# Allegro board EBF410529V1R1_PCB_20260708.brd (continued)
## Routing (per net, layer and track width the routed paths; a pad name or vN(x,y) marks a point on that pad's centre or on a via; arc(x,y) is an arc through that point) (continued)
VBUS5V0_TYPEC: length 54
  TOP w0.254: J10.B9 v1(29.3,86.28) v1(29.3,87.05) 30.12,87.05 v1(30.12,87.05) ; v1(29.25,80.59) v1(29.25,81.33) v1(29.25,82.13) 29.06,82.32 J10.A4 ; J10.B4 26.8,85.95 v1(26.54,86.21) v1(26.54,87.01) v1(25.74,87.01) ; J10.A9 26.56,82.25 v1(26.41,82.1) v1(26.41,81.3) v1(26.41,80.59)
  ART03 w0.254: v1(53.54,84.99) 53.16,84.61 50.47,84.61 48.51,82.65 45.75,82.65 44.37,84.02 36.47,84.02 33.05,80.59 v1(29.25,80.59)
  BOTTOM w0.254: v1(26.41,81.3) v1(26.41,82.1)
  BOTTOM w0.3: v1(53.54,84.99) 53.54,80.29 51.99,78.74 51.99,72.57 51.69,72.26 U11.2
VCC3V3_RTC_S5: length 27
  ART03 w0.381: v1(7.87,52.96) 7.87,56.06 6.96,56.97 3.84,56.97 2.92,57.89 v1(2.92,59.65)
  BOTTOM w0.254: U6.2 v1(2.92,59.65) ; R241.1 14.34,50.93 13.34,50.93 13.08,51.18 13.08,53.04 12.17,53.95 8.26,53.95 7.87,53.57 v1(7.87,52.96)
  BOTTOM w0.381: U6.2 3.75,60.51 C31.1 3.75,61.41 D9.2
VCC5V0_SYS_S5: length 253.3
  TOP w0.254: J3.6 15.69,60.8 15.44,60.55 J3.5 ; v1(23.5,49.5) 22.86,50.14 R198.2 ; J3.1 14.44,60.67 14.69,60.92 J3.2 ; v1(23.02,22.54) 21.7,22.54 19,19.83 19,16.92 20.73,15.19 v1(20.73,13.47) ; J3.7 15.94,60.49 16.19,60.74 J3.8 ; J3.3 14.94,60.61 15.19,60.86 J3.4
  TOP w0.381: J3.2 14.69,66.21 14.2,66.7 11.07,66.7 10.54,66.17 10.54,64.85 9.93,64.24 7.32,64.24 5.21,62.13 2.92,62.13 1.57,60.78 1.57,55.15 v2(2.29,54.43)
  BOTTOM w0.254: R6.2 C11.2 19.12,55.67 17.92,54.47 17.92,53.9 17.62,53.59 15.96,53.59 ; v1(20.73,13.47) 21.11,13.09 38.12,13.09 38.96,12.24 38.96,8.69 40.34,7.32 40.34,4.62 43.59,1.37 65.74,1.37 66.9,2.54 106.6,2.54 109.96,5.89 135,5.89 136.27,4.62 R4.1 ; v1(23.02,22.54) 22.78,22.77 22.78,43.97 23.5,44.68 v1(23.5,49.5) 21.41,51.58 16.74,51.58 15.82,52.5 v1(15.64,52.5)
  BOTTOM w0.381: v2(2.29,54.43) C32.1 2.29,56.32 2.79,56.82 U6.3
  vias: v1(14.84,54.1) v1(14.84,53.3) v1(14.84,52.5) v1(15.64,54.1) v1(15.64,53.3)
VCC5V0_USB20_HOST: length 24.3
  ART03 w0.762: J12.1 J12.7 135.44,80.42 129.49,80.42 128.14,79.07 120.2,79.07 118.31,77.18 J11.10
VCC_1V8_S3: length 60.5
  TOP w0.254: R159.1 v1(76.78,35.43) ; v1(61.78,36.3) 61.8,36.27 61.8,35.86 R158.1 ; J3.26 20.69,60.11 20.44,59.86 J3.25 v1(20.44,54.1)
  TOP w0.508: v1(93.01,27) 93.04,26.97 93.04,20.62 89.43,17.02 C133.1 C134.1 88.52,15.65 88.52,12.79 D58.2 93.72,5.82 J30.1
  ART03 w0.254: v1(20.44,52.1) 19.95,51.61 18.57,51.61 15.98,49.02 15.98,45.34 v1(15.49,44.85)
  PWR04 w0.254: v1(20.44,54.1) v1(20.44,53.1) v1(20.44,52.1)
  BOTTOM w0.254: R156.1 9.91,45.72 13.97,45.72 14.84,44.85 v1(15.49,44.85)
  vias: v1(92.21,27)
VCC_3V3_S0: length 30.3
  TOP w0.254: v1(18.44,54.1) J3.17 18.44,60.15 18.69,60.4 J3.18 ; J3.16 18.19,60.46 17.94,60.21 J3.15
  PWR04 w0.254: v1(18.44,54.1) v1(18.44,53.1) v1(18.44,52.1)
  BOTTOM w0.254: v1(126.54,20.5) 126.54,19.99 128.45,18.09 129.33,18.09 C20.1 130.49,18.09 132,18.09 C21.1 132.74,18.51 J4.4
  vias: v1(13.89,46.65) v1(14.69,46.65) v1(14.69,45.85) v1(15.49,45.85)
VCC_RTC: length 22.2
  ART03 w0.381: v1(5.21,50.87) 5.01,50.87 1.68,54.2 1.68,62.5 v2(1.88,62.7)
  BOTTOM w0.305: U5.8 7.61,50.84 8.08,51.31 C26.1 ; R157.1 R32.1
  BOTTOM w0.381: D9.3 v2(1.88,62.7) ; v1(5.21,50.87) 5.79,50.28 R157.1 8.64,50.29 C26.1
VCCA1V8_PLDO2_S0: length 3.5
  TOP w0.305: J3.23 19.94,54.6 v1(19.44,54.1)
  BOTTOM w0.254: R15.1 42.16,62.11 41.83,62.44 v1(41.19,62.44)
VDD_3V3: length 137.4
  TOP w0.203: U7.28 67.17,24.36 C35.1 67.57,24.46 U7.29 ; U8.28 83.4,24.36 C50.1 83.8,24.46 U8.29
  TOP w0.254: C33.1 v1(67.32,22.53) C34.1 C35.1 ; R77.1 v1(76.78,34.42) ; R34.1 v1(63.25,20.21) ; R21.1 v1(140.72,6.46) ; R35.1 v1(61.21,20.21) ; C50.1 C51.1 v1(83.55,22.52) C49.1 ; C176.1 v1(5.08,75.29) ; R145.1 v1(138.68,23.76) ; R46.1 73.28,23.5 L5.1 ; R22.1 v1(135.24,8.13) ; v1(60.53,35.2) 60.75,35.42 R53.1 ; R33.1 v1(64.26,20.21) ; R72.1 v1(76.78,32.26) ; v1(80.49,20.21) R57.1 ; R70.1 89.51,23.5 L7.1 ; R141.1 v1(109.02,52.84) R142.1 ; v1(79.48,20.21) R58.1 ; R48.1 R47.1 60.63,31.24 v1(60.54,31.15) ; R59.1 v1(82.52,20.21) ; R82.2 v1(43.43,82.61) ; R3.1 6.09,66.67 5.58,67.18 U28.5 ; R103.1 v1(77.89,51.32) ; R136.1 v1(78.96,51.32) ; R71.1 v1(76.78,31.11) ; R144.1 v1(137.67,23.76)
  TOP w0.381: U34.5 v1(28.7,14.02) ; L5.1 73.38,23 v1(73.38,22.45) ; R127.1 v1(108.46,33.63) ; U35.5 v1(22.48,14.02) ; L7.1 v1(89.81,22.45)
  TOP w0.508: v1(117.09,38.43) R148.1 C143.1 118.56,38.63 Q11.2
  TOP w0.762: 141.71,58.88 129.7,58.88 v1(129.59,58.99) ; 141.71,58.88 142.81,57.77 142.81,45.91 J32.17 ; 141.71,58.88 142.9,60.07 142.9,62.43 144.73,64.26 J32.1
  BOTTOM w0.254: R146.1 95.09,65.44 Q7.1 v1(93.6,65.85) ; v1(22.26,62.44) 23.07,62.44 R162.1 ; v1(90.25,66.09) R139.1 89.44,65.4 Q6.1 ; L9.1 22.11,59.28 v1(22.26,59.44) ; R91.1 29.53,56.45 v1(28.73,57.25) ; R150.1 v1(79.69,66.06) ; v1(20.94,65.15) 21.06,65.02 R235.1 R160.1 ; R240.1 R239.1 R189.1 R190.1 ; R240.1 v1(46.99,65.46) ; R240.1 R237.1 R238.1 R163.1 R188.1 ; R12.1 v1(139.33,4.06) ; L8.1 32.21,64.29 32.21,65.63 v1(31.69,66.15) 31.21,65.67 30.31,65.67 R236.1 ; v1(42.14,84.55) 42.18,84.55 R87.1 42.68,85.36 41.96,85.36 R97.2
  BOTTOM w0.381: C189.1 32.71,14.78 33.32,15.39 36.09,15.39 37.67,16.97 37.67,19.03 v1(37.67,19.04) 37.67,19.53 L16.1 ; C189.1 C196.1 v1(22.48,14.02) ; C189.1 v1(28.7,14.02) ; L15.2 53.18,17.34 v1(53.18,17.02) ; L17.1 v1(45.17,19.04)
  vias: v1(4.08,75.29) v1(13.13,41.8) v1(13.93,41.8) v1(13.93,41) v1(14.73,41.8) v1(50.85,74.4) v1(51.26,70.53) v1(52.37,70.54) v1(58.08,13.75) v1(58.08,12.75) v1(59.08,12.75) v1(124.64,16.26) v1(124.64,15.26) v1(125.64,16.26) v1(125.64,15.26) v1(128.59,59.99) v1(128.59,58.99) v1(129.59,59.99)
VDD_5V: length 59.8
  TOP w0.254: v1(104.29,15.76) R10.1 103,16.39 103,16.97 102.57,17.4 101.8,17.4 101.44,17.76 101.44,19.38 Q1.2 ; C154.1 v1(9.91,30.89) ; R126.1 114.17,40.06 114.53,39.7 114.53,38.38 v1(114.53,38.38) ; C152.1 v1(11.66,12.3) ; R167.1 v1(8.89,30.89)
  TOP w0.381: U35.3 v1(23.75,21.54) ; U34.3 v1(29.97,21.54)
  TOP w1.016: J32.4 J32.2
  ART03 w0.254: v1(7.45,46.35) v1(7.45,45.35)
  PWR04 w0.381: 146.29,64.31 J32.2 ; J32.2 147.27,65.29 ; J32.2 147.27,63.34 ; J32.4 147.27,62.75 ; J32.4 147.27,60.8 ; J32.4 146.29,61.77
  BOTTOM w0.254: C2.2 R1.2 11.15,63.96 11.15,55.45 10.41,54.71 6.73,54.71 ; Q10.1 84.21,65.14 84.66,64.69 85.23,64.69 R140.1 86.04,63.88 87.71,63.88 88.09,64.26 88.09,66.27 88.54,66.73 90.83,66.73 91.34,66.22 R147.1 ; U20.5 v1(136.05,85.79) ; C8.1 v2(4.2,55.25)
  BOTTOM w0.381: v1(23.75,21.54) 23.88,21.4 C197.1 23.88,20.79 24.54,20.14 29.39,20.14 30.11,20.86 C190.1 29.97,21.02 v1(29.97,21.54)
  vias: v1(9.75,24.79) v1(10.52,50.04) v1(10.52,49.11) v1(10.92,24.79) v1(11.66,11.5) v1(37.76,79.91) v1(38.26,80.41) v1(39.26,80.41) v1(40.98,73.92) v1(41.78,73.92) v1(63.99,14.16) v1(64.01,12.85) v1(64.76,14.15) v1(64.79,13.36) v1(83.57,66.85) v1(84.37,67.65) v1(84.37,66.85) v1(116.92,86.72) v1(116.92,85.72) v1(117.92,86.72) v1(117.92,85.72) v1(118.3,16.24) v1(119.3,16.24) v1(119.3,15.24) v1(135.05,84.79) v1(136.05,84.79) v2(4.2,54.25) v2(4.2,53.25) v2(5.2,54.25) v2(5.2,53.25)
BAT_RTC: length 7.1
  BOTTOM w0.381: D9.1 2.29,65.18 C24.1 2.29,66.76 D10.2 3.8,69.62 J5.1
BM8563_INT: length 13.1
  BOTTOM w0.107: U5.3 2.9,52.14 3.63,51.41 4.19,51.41 4.5,51.1 4.5,50.39 5.11,49.78 6.99,49.78 7.32,49.45 7.32,48.34 7.52,48.13 D18.1 8.43,49.08 R157.2 R32.2 9.95,49.58 10.85,49.58 Q3.1
BOOT_SARADC_IN0: length 212.7
  TOP w0.107: J3.94 37.69,61.61 39.48,59.82 40.19,59.82 v1(40.62,60.25)
  ART03 w0.107: v1(106.91,8.13) 106.53,8.51 106.53,20.42 105.36,21.59 105.36,35.79 111.94,42.37 111.94,45.29 111.5,45.73 v1(111.5,46.05)
  BOTTOM w0.107: v1(40.62,60.25) 41.03,59.84 41.03,57.9 39.52,56.39 39.52,48.87 40.13,48.27 40.13,36.55 38.66,35.08 38.66,31.01 38.86,30.81 38.86,27.79 37.74,26.67 37.74,23.93 40.91,20.76 40.91,9.94 42.57,8.28 42.57,5.45 45.18,2.84 64.96,2.84 67.67,5.56 105.51,5.56 106.91,6.96 v1(106.91,8.13) ; v1(111.5,46.05) 111.81,46.05 112.27,45.59 115.47,45.59 116.81,46.94 129.44,46.94 131.29,48.79 131.29,62.97 R27.2
CAM0_PWDN: length 81.7
  TOP w0.107: v1(33.69,66.15) 34.11,66.57 34.98,66.57 35.69,65.86 J3.86 ; v1(3.07,39.6) 2.13,39.6 1.85,39.32 1.85,20.17 2.59,19.43 4.67,19.43 4.75,19.35 J14.15
  ART03 w0.107: v1(3.07,39.6) 3.43,39.6 5.11,41.27 5.11,41.66 5.44,41.99 5.87,41.99 6.91,43.03 10.97,43.03 11.38,43.43 11.81,43.43 12.21,43.83 12.21,50.92 12.62,51.33 12.62,54.66 14.5,56.54 29.64,56.54 33.45,60.35 33.45,63.78 34.21,64.54 34.21,65.63 v1(33.69,66.15)
CAM0_RSTN: length 75.9
  TOP w0.107: J14.22 2.7,22.85 2.26,23.29 2.26,38.93 2.37,39.04 3.58,39.04 4.06,39.52 v1(4.06,39.6) ; J3.84 35.19,65.65 v1(34.69,66.15)
  ART03 w0.107: v1(4.06,39.6) 4.11,39.6 7.23,42.71 11.68,42.71 12.47,43.5 12.47,50.65 12.62,50.8 12.97,51.15 12.97,53.97 12.97,54.39 14.72,56.15 30.45,56.15 33.86,59.56 33.86,63.53 34.69,64.36 v1(34.69,66.15)
CAM1_PWDN: length 53.6
  TOP w0.107: J15.15 5.6,38.55 5.11,39.04 5.11,40.34 4.24,41.2 v1(4.06,41.2) ; J3.78 v1(33.69,65.15)
  ART03 w0.107: v1(33.69,65.15) 33.69,64.73 33.1,64.14 33.1,60.73 29.24,56.87 14.38,56.87 12.36,54.86 12.36,51.48 11.95,51.06 11.95,43.98 11.68,43.71 11.23,43.71 10.87,43.36 6.71,43.36 5.71,42.37 5.23,42.37 v1(4.06,41.2)
CAM1_RSTN: length 56.1
  TOP w0.107: v1(32.69,66.15) 33.19,65.65 J3.76 ; J15.22 3.91,42.05 v1(3.06,41.2)
  ART03 w0.107: v1(3.06,41.2) 3.48,41.2 5.13,42.85 5.13,43.08 5.77,43.71 10.68,43.71 10.71,43.74 10.71,43.74 10.97,44.01 10.97,44.25 11.69,44.96 11.69,51.17 12.08,51.56 12.08,55.21 14.56,57.69 20.8,57.69 21.11,57.38 21.72,57.38 22.03,57.69 29.42,57.69 32.64,60.91 32.64,64.31 33.2,64.87 33.2,65.64 v1(32.69,66.15)
CAM2_PWDN: length 76
  TOP w0.107: v1(36.16,61.29) 35.33,61.29 34.19,62.43 J3.80
  BOTTOM w0.107: v1(36.16,61.29) 36.58,60.87 36.58,59.39 35.43,58.24 35.43,55.3 34.26,54.13 34.26,53.01 33.42,52.17 33.42,49.96 32.79,49.33 32.79,37.03 32.48,36.72 32.48,29.18 30.73,27.43 30.73,23.06 31.7,22.1 31.7,20.14 29.64,18.08 28.24,18.08 27.01,16.85 13.95,16.85 12.12,15.01 11.25,15.01 10.72,15.54 8.84,15.54 7.53,16.85 J16.15
CAM2_RSTN: length 76
  TOP w0.107: v1(37.16,61.29) 36.75,61.7 35.48,61.7 34.69,62.49 J3.82
  BOTTOM w0.107: J16.22 7.76,13.35 8.99,14.58 12.24,14.58 14.07,16.41 27.2,16.41 28.42,17.63 29.74,17.63 32.09,19.97 32.09,27.9 32.94,28.75 32.94,36.63 33.18,36.87 33.18,49.08 34.65,50.55 34.65,53.93 35.81,55.09 35.81,58.08 37.16,59.42 v1(37.16,61.29)
CAM3_PWDN: length 67.3
  TOP w0.107: J18.15 3.24,57.37 2.67,56.79 2.67,55.96 3.56,55.07 3.56,53.39 1.57,51.41 1.57,44.09 2.62,43.05 v1(4.04,43.05) ; J3.72 32.19,65.47 32.01,65.65 31.19,65.65 v1(30.69,66.15)
  ART03 w0.107: v1(30.69,66.15) 31.19,65.65 31.19,61.93 28.13,58.86 14.59,58.86 9.75,54.03 9.75,51.79 8.28,50.32 8.28,49.67 7.94,49.33 7.16,49.33 4.6,46.76 4.6,44.5 4.04,43.94 v1(4.04,43.05)
CAM3_RSTN: length 74.2
  TOP w0.107: J18.22 4.63,60.87 3.43,59.66 3.43,58.22 2.26,57.05 2.26,55.75 3.16,54.85 3.16,53.6 1.17,51.61 1.17,41.42 v1(1.54,41.05) ; J3.74 v1(32.69,65.15)
  ART03 w0.107: v1(1.54,41.05) 2.12,41.63 3.35,41.63 4.65,42.93 4.65,43.21 5.87,44.43 10.57,44.43 11.38,45.24 11.38,51.31 11.79,51.72 11.79,55.48 14.63,58.32 22.76,58.32 23,58.08 28.13,58.08 31.62,61.57 31.62,64.08 v1(32.69,65.15)
CAM4_PWDN: length 66.8
  TOP w0.107: J3.88 36.19,62.32 v1(36.16,62.29) ; v1(8.89,29.89) 9.2,29.58 v1(23.94,29.58)
  BOTTOM w0.107: v1(8.89,29.89) 8.56,29.89 8.05,30.4 8.05,35.46 7.46,36.05 J17.15 ; v1(36.16,62.29) 35.87,62.29 35.47,61.88 35.47,59.93 34.29,58.75 34.29,56.11 31.57,53.39 31.57,37.54 31.36,37.33 31.36,30.35 30.1,29.08 24.44,29.08 v1(23.94,29.58)
CAM4_RSTN: length 66
  TOP w0.107: J3.90 36.69,62.5 36.9,62.29 v1(37.16,62.29) ; v1(8.89,28.89) 9.2,28.58 v1(23.94,28.58)
  BOTTOM w0.107: v1(23.94,28.58) 24.38,28.14 29.77,28.14 31.77,30.14 31.77,37.13 32,37.36 32,52.43 32.51,52.93 32.51,53.54 34.72,55.75 34.72,58.78 35.74,59.79 35.74,61.59 35.97,61.82 36.69,61.82 v1(37.16,62.29) ; v1(8.89,28.89) 8.52,28.89 7.52,29.9 7.52,32.34 7.3,32.55 J17.22
CAN0_H: length 22.7
  TOP w0.254: R205.1 30.99,11.57 30.99,9.01 30.18,8.2 20.1,8.2 19.59,7.7 19.59,6.56 20.1,6.05 J29.1 ; R205.1 30.99,12.06 30.99,12.99 30.86,13.11 30.86,13.84 31.24,14.22 U34.7 ; R205.1 D57.1
CAN0_L: length 22.6
  TOP w0.254: U34.6 29.97,14.22 30.35,13.84 30.35,12.9 30.48,12.78 30.48,12.06 R205.2 ; R205.2 30.48,11.57 30.48,9.22 29.97,8.71 19.89,8.71 19.08,7.91 19.08,6.56 18.57,6.05 J29.2 ; R205.2 D47.1
CAN0_RX_M2: length 54.3
  TOP w0.107: v1(35.81,59.23) 35.64,59.23 35.47,59.41 28.76,59.41 26.69,61.47 J3.50 ; U34.4 v1(28.7,21.54)
  BOTTOM w0.107: v1(35.81,59.23) 35.11,58.53 35.11,55.59 33.38,53.86 33.38,53.12 32.39,52.13 32.39,37.19 32.16,36.96 32.16,29.82 30.12,27.79 30.12,22.96 v1(28.7,21.54)
CAN0_TX_M2: length 59.4
  TOP w0.107: U34.1 v1(32.51,19.02) ; J3.48 26.19,60.33 26.59,59.93 27.77,59.93 28.56,59.15 35.09,59.15 35.51,58.72 37.1,58.72 v1(37.62,59.25)
  BOTTOM w0.107: v1(32.51,19.02) 33.45,19.96 33.45,27.95 34,28.5 34,36.21 35.16,37.37 35.16,49.48 35.71,50.04 35.71,53.6 36.62,54.51 36.62,57.43 37.08,57.89 37.08,58.71 v1(37.62,59.25)
CAN1_H: length 23.2
  TOP w0.254: R206.1 24.64,11.57 24.64,10.33 23.83,9.53 19.11,9.53 18.22,8.64 12.81,8.64 12.04,7.87 12.04,6.56 12.55,6.05 J29.3 ; R206.1 D30.1 ; R206.1 24.64,12.06 24.64,13.87 25.02,14.25 U35.7
CAN1_L: length 23.3
  TOP w0.254: R206.2 24.13,11.57 24.13,10.54 23.62,10.03 18.9,10.03 18.01,9.14 12.6,9.14 11.53,8.08 11.53,6.56 11.02,6.05 J29.4 ; R206.2 D25.1 ; R206.2 24.13,12.06 24.13,13.87 23.75,14.25 U35.6
CAN1_RX_M3: length 64.4
  TOP w0.107: J3.151 51.94,27.58 47.6,23.24 28.09,23.24 26.92,22.07 26.92,19.41 26.19,18.67 22.86,18.67 22.48,19.05 U35.4
CAN1_TX_M3: length 57.4
  TOP w0.107: U35.1 26.29,22.02 27.91,23.65 47.4,23.65 51.44,27.69 J3.149
CTP_INT: length 137.9
  TOP w0.107: J3.175 59.44,20.75 60.71,19.48 61.58,19.48 v1(62.21,18.85) ; v1(138.67,27.51) 138.2,27.51 137.74,27.05 137.74,24.84 137.16,24.26 137.16,22.61 R144.2 138.53,21.24 138.53,19.53 140.52,17.55 J13.11
  ART03 w0.107: v1(62.21,18.85) 75.69,18.85 75.95,19.1 91.47,19.1 99.54,27.18 100.16,27.18 v1(100.65,27.66)
  BOTTOM w0.107: v1(100.65,27.66) 109.08,27.66 110.66,26.09 121.92,26.09 122.58,26.75 124.79,26.75 127.76,29.72 137.77,29.72 138.67,28.82 v1(138.67,27.51)
CTP_RST: length 138.9
  TOP w0.107: J13.12 140.63,18.05 138.92,19.76 138.92,21.87 R145.2 138.18,22.61 138.18,26.81 138.39,27.03 139.19,27.03 v1(139.67,27.51) ; v1(59.97,19.62) 59.96,19.62 59.96,19.68 58.94,20.7 J3.173
  ART03 w0.107: v1(59.97,19.62) 60.31,19.28 75.54,19.28 75.75,19.49 91.27,19.49 99.44,27.66 v1(99.65,27.66)
  BOTTOM w0.107: v1(139.67,27.51) 139.67,28.48 138.02,30.12 129.16,30.12 128.6,30.68 128.12,30.68 126.19,28.75 125.58,28.75 124.46,27.64 122.3,27.64 121.74,27.08 117.55,27.08 116.95,26.47 110.89,26.47 109.24,28.12 100.1,28.12 v1(99.65,27.66)
DP_TX_AUXN: length 86
  TOP w0.135: J3.295 89.44,54.7 89.53,54.61 89.53,53.24 arc(89.5,53.08) 89.41,52.95 v1(89.27,52.81)
  ART03 w0.135: v1(89.27,52.81) 89.35,52.73 arc(89.39,52.66) 89.41,52.59 89.41,52.45 arc(89.39,52.39) 89.36,52.33 89.27,52.25 85.93,52.25 arc(85.69,52.29) 85.5,52.43 79.19,58.73 arc(78.67,59.5) 78.49,60.41 78.49,61.02 arc(78.37,61.62) 78.03,62.13 74.85,65.31 arc(74.13,65.8) 73.27,65.97 65.46,65.97 arc(64.97,65.87) 64.55,65.6 64.45,65.49 arc(64.14,65.28) 63.77,65.21 53.63,65.21 arc(52.72,65.39) 51.95,65.91 48.91,68.94 arc(48.04,69.53) 47.01,69.73 34.9,69.73 arc(34.07,69.9) 33.37,70.37 32.91,70.82 arc(32.5,71.1) 32.01,71.2 28.09,71.2 arc(27.18,71.38) 26.4,71.89 25.32,72.97 arc(25.04,73.16) 24.71,73.23 24.16,73.23 arc(23.58,73.34) 23.08,73.68 22.81,73.94 arc(22.62,74.23) 22.56,74.57 22.56,74.85 arc(22.49,75.18) 22.3,75.46 21.9,75.87 arc(21.75,75.96) 21.58,76 21.57,76 arc(21.5,76.01) 21.44,76.05 v1(21.33,76.16)
  BOTTOM w0.135: v1(21.33,76.16) 21.47,76.02 arc(21.61,75.93) 21.77,75.9 22.28,75.9 arc(22.52,75.94) 22.72,76.08 22.95,76.31 arc(23.02,76.41) 23.05,76.54 23.05,76.61 arc(23.01,76.77) 22.92,76.91 C106.2
DP_TX_AUXP: length 88.4
  TOP w0.135: J3.297 89.94,54.7 89.85,54.61 89.85,53.05 arc(89.92,52.88) 90.09,52.81 v1(90.11,52.81)
  ART03 w0.135: v1(21.33,75.32) 21.3,75.35 21.3,75.55 arc(21.34,75.64) 21.44,75.68 21.58,75.68 arc(21.63,75.67) 21.68,75.64 22.08,75.24 arc(22.2,75.06) 22.24,74.85 22.24,74.57 arc(22.33,74.11) 22.59,73.72 22.86,73.45 arc(23.46,73.06) 24.16,72.92 24.71,72.92 arc(24.92,72.87) 25.1,72.75 26.18,71.67 arc(27.06,71.09) 28.09,70.88 32.01,70.88 arc(32.38,70.81) 32.69,70.6 33.15,70.15 arc(33.95,69.61) 34.9,69.42 47.01,69.42 arc(47.92,69.24) 48.69,68.72 51.73,65.69 arc(52.6,65.1) 53.63,64.9 63.77,64.9 arc(64.26,64.99) 64.67,65.27 64.78,65.38 arc(65.09,65.59) 65.46,65.66 73.27,65.66 arc(74.01,65.51) 74.63,65.09 77.81,61.91 arc(78.09,61.5) 78.18,61.02 78.18,60.41 arc(78.39,59.38) 78.97,58.51 85.27,52.21 arc(85.57,52.01) 85.93,51.94 87.28,51.94 arc(87.37,51.9) 87.4,51.81 arc(87.44,51.73) 87.53,51.69 87.82,51.69 arc(87.9,51.73) 87.94,51.81 arc(87.98,51.9) 88.06,51.94 88.36,51.94 arc(88.44,51.9) 88.48,51.81 arc(88.52,51.73) 88.6,51.69 88.89,51.69 arc(88.98,51.73) 89.02,51.81 arc(89.05,51.9) 89.14,51.94 89.4,51.94 89.58,52.11 arc(89.68,52.27) 89.72,52.45 89.72,52.72 arc(89.76,52.82) 89.85,52.86 90.06,52.86 v1(90.11,52.81)
  BOTTOM w0.135: v1(21.33,75.32) 21.33,75.45 21.41,75.52 arc(21.47,75.57) 21.55,75.58 22.28,75.58 arc(22.64,75.65) 22.94,75.86 23.17,76.09 arc(23.31,76.29) 23.36,76.54 23.36,76.55 arc(23.39,76.69) 23.47,76.81 C105.2
DSI_VDD3V3: length 23.5
  BOTTOM w0.635: U25.1 121.78,14.84 C145.1 C146.1 122.82,13.64 123.11,13.34 140.72,13.34 141.69,14.31 142.55,14.31
  vias: v1(142.49,14.05) v1(144.5,14.55)
DSI_VDD5V: length 29.5
  BOTTOM w0.762: U24.1 116.58,14.84 C138.1 C139.1 117.61,13.16 118.63,12.14 142.2,12.14 142.73,12.67
  vias: v1(142.49,13.04) v1(144.5,13.05)
EARPHONE_CTL: length 27.3
  TOP w0.107: J3.129 46.44,54.04 v1(46.94,53.54) ; R95.2 48.38,70.59 v1(48.01,70.22)
  BOTTOM w0.107: v1(46.94,53.54) 47.37,53.97 47.37,54.64 47.7,54.97 50.44,54.97 52.6,57.12 52.6,59.94 51.28,61.27 51.28,62.61 52.2,63.53 52.2,65.51 48.01,69.69 v1(48.01,70.22)
ETH0_MCLK_M0: length 106.3
  TOP w0.132: J3.75 32.94,55.89 32.94,54.74 33.4,54.28 33.4,49.83 35.18,48.06 35.18,25.02 34.62,24.46 26.94,24.46 v1(25.02,22.54) ; v1(72.97,20.21) 75.56,22.8 75.56,28.32 74.85,29.03 R49.1
  ART03 w0.152: v1(72.97,20.21) 72.48,19.71 60.71,19.71 60.35,20.07 58.67,20.07 58.29,19.68 54.23,19.68 53.72,19.18 45.85,19.18 45.59,19.43 44.83,19.43 44.45,19.05 43.18,19.05 42.67,18.54 37.47,18.54 37.08,18.92 35.94,18.92 35.38,19.48 25.96,19.48 25.53,19.91 25.53,22.03 v1(25.02,22.54)
ETH0_MDC_M0: length 75.9
  TOP w0.107: J3.41 24.44,54.54 24.13,54.23 24.13,52.37 24.54,51.96 24.54,30.85 v1(24.95,30.44) ; U7.13 62.92,30.92 62.73,31.11 62.73,31.75 R48.2 61.71,32.77 60.31,32.77 60.1,32.98 60.1,37.45 60.84,38.19 v1(60.84,38.21)
  ART03 w0.107: v1(60.84,38.21) 60.01,38.21 58.68,36.88 34.29,36.88 31.33,33.92 27.47,33.92 25.4,31.85 25.4,30.89 v1(24.95,30.44)
ETH0_MDIO_M0: length 77.6
  TOP w0.107: v1(24.95,31.24) 24.95,52.14 24.43,52.65 24.43,54.03 24.94,54.53 J3.43 ; v1(60.84,39.01) 60.84,38.99 59.74,37.89 59.74,31.06 60.07,30.74 61.72,30.74 R47.2 62.8,30.66 62.99,30.66 63.13,30.52 U7.14
  ART03 w0.107: v1(24.95,31.24) 24.95,31.93 27.34,34.33 31.21,34.33 34.04,37.16 58.56,37.16 60.41,39.01 v1(60.84,39.01)
ETH0_RSTN: length 67.9
  TOP w0.107: v1(61.91,39.01) 61.37,38.47 61.37,37.92 61.01,37.57 D59.1 ; v1(25.95,31.24) 25.35,31.84 25.35,52.32 24.87,52.81 24.87,53.85 25.44,54.42 J3.45
  ART03 w0.107: v1(25.95,31.24) 25.95,31.75 27.62,33.42 31.41,33.42 34.49,36.5 58.84,36.5 60.11,37.77 61.03,37.77 61.25,37.98 61.25,38.36 61.9,39.01 v1(61.91,39.01)
ETH0_RXCLK_M0: length 72.3
  TOP w0.132: v1(34.35,26.35) 34.32,26.39 34.32,47.7 32.54,49.48 32.54,54.15 31.94,54.75 31.94,55.89 J3.71 ; R41.1 v1(66.29,22.52) R44.1
  ART03 w0.152: v1(34.35,26.35) 34.35,25.66 34.51,25.51 34.81,25.51 34.96,25.66 34.96,26.4 35.12,26.56 35.4,26.56 35.55,26.4 35.55,25.64 35.7,25.48 36.01,25.48 36.16,25.64 36.16,26.4 36.31,26.56 36.59,26.56 36.74,26.4 36.74,25.61 36.89,25.46 37.2,25.46 37.35,25.61 37.35,26.44 37.5,26.59 39.62,26.59 39.93,26.29 39.93,23.6 40.08,23.44 65.37,23.44 v1(66.29,22.52)
ETH0_RXCTL_M0: length 72.7
  TOP w0.132: v1(32.97,26.35) 32.97,47.19 31.32,48.84 31.32,48.87 31.26,48.93 31.26,54.26 30.94,54.58 J3.67 ; R45.1 v1(65.28,22.52) R42.1
  ART03 w0.152: v1(32.97,26.35) 32.42,26.9 31.37,26.9 31.01,26.54 31.01,24.89 35.53,20.37 57.73,20.37 58.45,21.08 63.84,21.08 v1(65.28,22.52)
ETH0_RXD0_M0: length 72.4
  TOP w0.132: R37.1 v1(64.26,22.52) R33.2 ; J3.63 29.94,54.41 30.4,53.95 30.4,48.57 31.97,47 31.97,25.85 v1(31.47,25.35)
  ART03 w0.152: v1(64.26,22.52) 64.26,22.23 63.58,21.54 57.61,21.54 57.43,21.36 57.43,20.98 57.28,20.83 56.97,20.83 56.82,20.98 56.82,21.29 56.64,21.46 56.36,21.46 56.21,21.31 56.21,20.98 56.06,20.83 55.75,20.83 55.6,20.98 55.6,21.29 55.42,21.46 55.14,21.46 54.99,21.31 54.99,20.98 54.84,20.83 54.53,20.83 54.38,20.98 54.38,21.29 54.2,21.46 53.92,21.46 53.77,21.31 53.77,20.98 53.62,20.83 52.83,20.83 52.45,21.21 51.82,21.21 51.44,20.83 47.52,20.83 47.14,21.21 46.61,21.21 46.23,20.83 39.93,20.83 39.52,21.23 38.76,21.23 38.4,20.88 35.81,20.88 31.47,25.22 v1(31.47,25.35)
ETH0_RXD1_M0: length 70.9
  TOP w0.132: v1(33.97,25.35) 33.45,25.87 33.45,47.32 31.67,49.1 31.67,54.43 31.44,54.66 J3.69 ; R36.1 v1(63.25,22.52) R34.2
  ART03 w0.152: v1(33.97,25.35) 33.97,25.01 34.24,24.74 37.57,24.74 37.8,24.51 37.8,23.27 38.07,22.99 38.47,22.99 38.78,23.29 38.78,25.04 38.62,25.2 38.1,25.2 37.97,25.32 37.97,25.68 38.13,25.83 39.23,25.83 39.39,25.68 39.39,23.3 39.7,22.99 62.78,22.99 v1(63.25,22.52)
ETH0_RXD2_M0: length 70.4
  TOP w0.132: J3.61 29.44,54.33 29.97,53.8 29.97,48.39 31.47,46.89 v1(31.47,26.35) ; R39.1 v1(62.23,22.52) R43.1
  ART03 w0.152: v1(31.47,26.35) 32.15,26.35 32.51,25.98 32.51,24.99 36.04,21.46 37.06,21.46 37.47,21.87 39.73,21.87 40.26,21.34 43.54,21.34 43.69,21.49 43.69,21.82 43.84,21.97 44.15,21.97 44.3,21.82 44.3,21.49 44.45,21.34 44.75,21.34 44.91,21.49 44.91,21.82 45.06,21.97 45.36,21.97 45.52,21.82 45.52,21.49 45.67,21.34 45.95,21.34 46.36,21.74 47.47,21.74 47.9,21.31 48.31,21.31 48.46,21.46 48.46,21.84 48.61,22 48.92,22 49.07,21.84 49.07,21.46 49.22,21.31 49.53,21.31 49.68,21.46 49.68,21.84 49.83,22 50.14,22 50.29,21.84 50.29,21.46 50.44,21.31 50.75,21.31 50.9,21.46 50.9,21.84 51.05,22 61.71,22 v1(62.23,22.52)
ETH0_RXD3_M0: length 70.1
  TOP w0.132: J3.65 30.44,54.5 30.84,54.1 30.84,48.74 32.47,47.11 32.47,25.85 v1(32.97,25.35) ; R35.2 v1(61.21,22.52) R40.1
  ART03 w0.152: v1(61.21,22.52) 42.98,22.52 42.83,22.37 42.83,21.97 42.67,21.82 42.37,21.82 42.22,21.97 42.22,22.37 42.06,22.52 41.76,22.52 41.61,22.37 41.61,21.97 41.45,21.82 40.69,21.82 40.06,22.45 37.85,22.45 37.29,23.01 37.29,23.98 37.13,24.13 36.8,24.13 36.65,23.98 36.65,22.17 36.5,22.02 36.22,22.02 36.04,22.2 36.04,23.95 35.86,24.13 35.58,24.13 35.43,23.98 35.43,23.34 35.28,23.19 35,23.19 34.82,23.37 34.82,23.95 34.65,24.13 34.19,24.13 v1(32.97,25.35)
ETH0_TXCLK_M0: length 67.7
  TOP w0.132: v1(26.93,29.58) 26.93,44.95 26.29,45.59 26.29,52.58 25.94,52.93 J3.47 ; U7.20 63.02,28.12 v1(62.76,27.86)
  ART03 w0.152: v1(62.76,27.86) 62.33,27.43 60.2,27.43 59.61,28.02 38.66,28.02 38.07,28.6 30.91,28.6 29.77,27.46 27.28,27.46 27.08,27.66 27.08,27.97 27.25,28.14 27.71,28.14 27.94,28.37 27.94,28.73 27.08,29.58 v1(26.93,29.58)
ETH0_TXCTL_M0: length 67.3
  TOP w0.132: v1(61.16,27.86) 61.69,28.39 62.89,28.39 63.02,28.52 U7.19 ; J3.53 27.44,54.04 27.91,53.57 27.91,47.12 28.93,46.11 28.93,29.08 v1(28.44,28.58)
  ART03 w0.152: v1(61.16,27.86) 60.4,27.86 59.79,28.47 42.7,28.47 42.55,28.63 42.55,28.83 42.39,28.98 42.09,28.98 41.94,28.83 41.94,28.6 41.78,28.45 41.5,28.45 41.38,28.57 41.38,28.85 41.22,29 40.78,29 40.63,28.85 40.63,28.65 40.48,28.5 40.17,28.5 40.02,28.65 40.02,28.85 39.87,29 39.56,29 39.41,28.85 39.41,28.65 39.26,28.5 38.95,28.5 38.8,28.65 38.8,28.88 38.62,29.06 30.71,29.06 29.59,27.94 28.65,27.94 28.44,28.16 v1(28.44,28.58)
ETH0_TXD0_M0: length 67.5
  TOP w0.132: J3.57 28.44,54.21 28.85,53.8 28.85,47.6 29.97,46.48 29.97,29.12 v1(29.44,28.58) ; U7.18 62.82,28.92 v1(62.76,28.86)
  ART03 w0.152: v1(29.44,28.58) 30.37,29.51 42.95,29.51 43.1,29.36 43.1,29.08 43.26,28.93 43.56,28.93 43.71,29.08 43.71,29.36 43.87,29.51 44.15,29.51 44.3,29.36 44.3,29.11 44.45,28.96 44.75,28.96 44.91,29.11 44.91,29.36 45.06,29.51 45.36,29.51 45.52,29.36 45.52,29.11 45.67,28.96 45.97,28.96 46.13,29.11 46.13,29.36 46.28,29.51 46.58,29.51 46.74,29.36 46.74,29.11 46.89,28.96 47.19,28.96 47.35,29.11 47.35,29.36 47.5,29.51 47.8,29.51 47.96,29.36 47.96,29.11 48.11,28.96 48.41,28.96 48.56,29.11 48.56,29.36 48.72,29.51 49,29.51 49.19,29.32 49.19,29.11 49.34,28.96 59.97,28.96 60.6,28.32 62.22,28.32 v1(62.76,28.86)
ETH0_TXD1_M0: length 67.3
  TOP w0.132: v1(28.44,29.54) 28.44,45.94 27.46,46.91 27.46,53.44 26.94,53.96 J3.51 ; U7.17 61.62,29.32 v1(61.16,28.86)
  ART03 w0.152: v1(28.44,29.54) 28.44,29.58 28.82,29.97 49.4,29.97 49.93,29.45 50.14,29.45 50.3,29.6 50.3,29.82 50.45,29.97 50.75,29.97 50.91,29.82 50.91,29.59 51.06,29.44 51.36,29.44 51.52,29.59 51.52,29.82 51.67,29.97 51.97,29.97 52.13,29.82 52.13,29.59 52.28,29.44 52.58,29.44 52.73,29.59 52.73,29.82 52.89,29.97 53.19,29.97 53.34,29.82 53.34,29.59 53.5,29.44 53.78,29.44 53.93,29.59 53.93,29.82 54.08,29.97 54.39,29.97 54.54,29.82 54.54,29.59 54.69,29.44 55,29.44 55.15,29.59 55.15,29.82 55.3,29.97 55.61,29.97 55.76,29.82 55.76,29.59 55.91,29.44 56.21,29.44 56.37,29.59 56.37,29.82 56.52,29.97 56.82,29.97 56.98,29.82 56.98,29.59 57.13,29.44 60.17,29.44 60.75,28.86 v1(61.16,28.86)
ETH0_TXD2_M0: length 67.2
  TOP w0.132: U7.16 62.91,29.72 v1(62.76,29.86) ; v1(29.44,29.54) 29.44,46.33 28.4,47.37 28.4,53.67 27.94,54.13 J3.55
  ART03 w0.152: v1(62.76,29.86) 62.33,29.43 60.92,29.43 59.92,30.43 59.62,30.43 59.47,30.28 59.47,30.1 59.32,29.95 59.01,29.95 58.86,30.1 58.86,30.28 58.71,30.43 58.4,30.43 58.25,30.28 58.25,30.1 58.1,29.95 57.79,29.95 57.64,30.1 57.64,30.28 57.49,30.43 28.39,30.43 27.94,29.97 27.94,29.37 28.24,29.07 28.96,29.07 v1(29.44,29.54)
ETH0_TXD3_M0: length 68.2
  TOP w0.132: v1(61.16,29.86) 61.6,30.3 62.94,30.3 63.12,30.12 U7.15 ; v1(27.44,28.58) 27.97,29.11 27.97,45.74 27.03,46.68 27.03,53.29 26.44,53.87 J3.49
  ART03 w0.152: v1(27.44,28.58) 27.27,28.58 26.47,29.39 26.47,29.79 26.75,30.07 27.38,30.07 28.19,30.89 60.14,30.89 v1(61.16,29.86)
ETH1_MCLK_M0: length 71
  TOP w0.132: J3.113 42.44,54.36 45.72,51.08 v1(45.72,35.05) ; R73.1 v1(90.66,29.03)
  ART03 w0.152: v1(90.66,29.03) 86,29.03 82.6,32.44 80.87,32.44 77.47,35.84 60.32,35.84 59.53,35.05 v1(45.72,35.05)
ETH1_MDC_M0: length 75.4
  TOP w0.107: v1(36.97,33.25) 37.47,33.74 37.47,48.04 35.03,50.48 35.03,54.69 34.94,54.77 J3.83 ; v1(61.91,37.41) 63.34,38.84 68.05,38.84 70.74,36.14 75.06,36.14 75.84,35.36 75.84,33.35 76.43,32.77 77.97,32.77 R72.2 78.98,31.75 78.98,31.24 79.3,30.92 U8.13
  ART03 w0.107: v1(36.97,33.25) 36.56,33.66 36.56,34.81 37.47,35.72 59.16,35.72 60.44,37 61.5,37 v1(61.91,37.41)
ETH1_MDIO_M0: length 72.2
  TOP w0.107: J3.81 34.44,54.71 34.67,54.48 34.67,50.27 36.97,47.96 v1(36.97,34.25) ; v1(62.71,37.41) 63.75,38.46 67.95,38.46 70.61,35.79 74.85,35.79 75.44,35.2 75.44,32.99 76.71,31.72 77.87,31.72 R71.2 78.88,30.71 79.15,30.71 79.34,30.52 U8.14
  ART03 w0.107: v1(36.97,34.25) 36.97,34.6 37.83,35.46 59.36,35.46 60.63,36.73 62.03,36.73 v1(62.71,37.41)
ETH1_RSTN: length 70.2
  TOP w0.107: D60.1 70.87,36.58 68.17,39.27 62.97,39.27 v1(61.91,38.21) ; J3.79 33.94,54.6 34.26,54.28 34.26,50.09 36.47,47.88 36.47,33.75 v1(35.97,33.25)
  ART03 w0.107: v1(35.97,33.25) 35.56,33.66 35.56,34.42 37.25,36.11 58.99,36.11 60.27,37.38 61.23,37.38 61.91,38.06 v1(61.91,38.21)
ETH1_RXCLK_M0: length 74.4
  TOP w0.132: v1(44.78,27.15) 44.78,51.03 41.44,54.37 J3.109 ; R59.2 v1(82.52,22.52) R67.1
  ART03 w0.152: v1(44.78,27.15) 59.33,27.15 60.15,26.34 63.91,26.34 64.67,27.1 67.83,27.1 68.35,26.58 69.25,26.58 71.04,24.79 79.15,24.79 79.3,24.64 79.3,23.85 79.45,23.7 79.76,23.7 79.91,23.85 79.91,24.64 80.06,24.79 80.44,24.79 80.62,24.61 80.62,23.19 80.82,22.99 82.05,22.99 v1(82.52,22.52)
ETH1_RXCTL_M0: length 74.5
  TOP w0.132: J3.103 39.94,53.3 42.82,50.43 42.82,25.64 v1(42.32,25.14) ; R69.1 v1(81.51,22.52) R68.1
  ART03 w0.152: v1(42.32,25.14) 42.8,24.66 58.39,24.66 58.88,24.18 67.23,24.18 69.85,21.56 80.56,21.56 v1(81.51,22.52)
ETH1_RXD0_M0: length 73.7
  TOP w0.132: J3.99 38.94,53.06 41.88,50.11 41.88,26.58 v1(42.32,26.14) ; R60.1 v1(80.49,22.52) R57.2
  ART03 w0.152: v1(80.49,22.52) 80.49,22.28 80.21,22 77,22 76.85,22.15 76.85,22.5 76.69,22.66 76.39,22.66 76.24,22.5 76.24,22.15 76.08,22 70.03,22 67.41,24.61 59.13,24.61 58.57,25.17 43.29,25.17 v1(42.32,26.14)
ETH1_RXD1_M0: length 73.2
  TOP w0.132: R58.2 v1(79.48,22.52) R61.1 ; J3.105 40.44,53.44 43.32,50.56 v1(43.32,27.14)
  ART03 w0.152: v1(43.32,27.14) 43.67,27.14 44.17,26.64 59.19,26.64 59.92,25.91 64.61,25.91 64.76,26.06 64.76,26.52 64.91,26.67 65.22,26.67 65.37,26.52 65.37,26.06 65.52,25.91 65.83,25.91 65.98,26.06 65.98,26.52 66.13,26.67 66.44,26.67 66.59,26.52 66.59,26.06 66.74,25.91 67.05,25.91 67.2,26.06 67.2,26.52 67.35,26.67 67.66,26.67 67.81,26.52 67.81,26.06 67.96,25.91 68.26,25.91 68.5,26.15 69.07,26.15 70.97,24.26 78,24.26 79.48,22.78 v1(79.48,22.52)
ETH1_RXD2_M0: length 72.6
  TOP w0.132: R63.1 v1(78.46,22.52) R65.1 ; J3.101 39.44,53.17 42.32,50.29 v1(42.32,27.14)
  ART03 w0.152: v1(42.32,27.14) 42.8,26.66 43.52,26.66 44.02,26.16 58.98,26.16 59.66,25.48 67.77,25.48 67.99,25.25 68.21,25.25 68.68,25.72 68.89,25.72 69.11,25.5 69.11,25.29 68.64,24.82 68.64,24.61 68.86,24.39 69.07,24.39 69.54,24.86 69.76,24.86 69.97,24.64 69.97,24.43 69.5,23.96 69.5,23.74 69.7,23.55 77.67,23.55 78.46,22.76 v1(78.46,22.52)
ETH1_RXD3_M0: length 72.6
  TOP w0.132: R66.1 v1(77.44,22.52) R64.1 ; J3.107 40.94,53.63 43.76,50.81 43.76,26.59 v1(43.32,26.14)
  ART03 w0.152: v1(43.32,26.14) 43.78,25.68 58.75,25.68 59.39,25.04 67.59,25.04 70.06,22.58 70.41,22.58 70.59,22.76 70.59,22.96 70.71,23.09 70.99,23.09 71.15,22.94 71.15,22.56 71.27,22.43 71.64,22.43 71.79,22.58 71.79,22.96 71.94,23.11 72.25,23.11 72.4,22.96 72.4,22.58 72.55,22.43 72.86,22.43 73.01,22.58 73.01,22.96 73.16,23.11 73.67,23.11 73.82,22.96 73.82,22.58 73.98,22.43 74.28,22.43 74.43,22.58 74.43,22.96 74.59,23.11 74.89,23.11 75.04,22.96 75.04,22.58 75.2,22.43 75.5,22.43 75.65,22.58 75.65,22.96 75.8,23.11 76.85,23.11 v1(77.44,22.52)
ETH1_TXCLK_M0: length 69
  TOP w0.132: v1(78.99,27.86) 79.25,28.12 U8.20 ; v1(39.1,32.25) 39.25,32.39 39.25,48.86 36.44,51.67 J3.89
  ART03 w0.152: v1(39.1,32.25) 39.1,32.02 39.32,31.8 39.6,31.8 39.75,31.95 39.75,32.13 39.9,32.28 40.21,32.28 40.36,32.13 40.36,31.95 40.51,31.8 63.7,31.8 65.05,30.45 66.29,30.45 66.65,30.1 66.65,29.72 66.85,29.51 67.41,29.51 67.59,29.34 70.89,29.34 71.37,28.85 72.62,28.85 73.91,27.56 74.73,27.56 74.9,27.38 77.65,27.38 78.13,27.86 v1(78.99,27.86)
ETH1_TXCTL_M0: length 68.3
  TOP w0.132: v1(77.39,27.86) 77.92,28.39 79.17,28.39 79.3,28.52 U8.19 ; v1(41,32.3) 40.56,32.73 40.56,49.78 37.44,52.9 J3.93
  ART03 w0.152: v1(41,32.3) 62.93,32.3 63.22,32.59 63.98,32.59 65.25,31.32 66.32,31.32 66.65,30.99 66.65,30.78 66.98,30.45 67.56,30.45 68.25,29.77 71.07,29.77 71.55,29.29 71.84,29.29 71.99,29.44 71.99,29.67 72.15,29.82 72.45,29.82 72.6,29.67 72.6,29.44 72.76,29.29 73.03,29.29 73.15,29.41 73.15,29.62 73.34,29.81 73.63,29.81 73.79,29.65 73.79,28.57 73.94,28.42 74.57,28.42 75.13,27.86 v1(77.39,27.86)
ETH1_TXD0_M0: length 68.9
  TOP w0.132: v1(37.93,33.25) 38.38,33.7 38.38,48.36 35.94,50.8 J3.87 ; v1(78.99,28.86) 79.05,28.92 U8.18
  ART03 w0.152: v1(78.99,28.86) 78.99,28.5 78.82,28.32 75.41,28.32 74.82,28.92 74.82,29.58 74.07,30.33 68.43,30.33 67.45,31.3 67.02,31.3 65.99,32.33 64.9,32.33 64.11,33.12 62.94,33.12 62.64,32.82 40.76,32.82 40.34,33.25 v1(37.93,33.25)
ETH1_TXD1_M0: length 68.7
  TOP w0.132: v1(41,33.3) 41,49.99 37.94,53.04 J3.95 ; U8.17 77.85,29.32 v1(77.39,28.86)
  ART03 w0.152: v1(77.39,28.86) 75.62,28.86 75.41,29.07 75.41,29.5 75.58,29.67 76.14,29.67 76.31,29.84 76.31,30.29 76.1,30.51 74.83,30.51 74.52,30.81 71.83,30.81 71.68,30.96 71.68,31.47 71.53,31.62 71.22,31.62 71.07,31.47 71.07,30.91 70.92,30.76 68.71,30.76 67.64,31.83 67.21,31.83 65.41,33.63 60.4,33.63 60.07,33.3 v1(41,33.3)
ETH1_TXD2_M0: length 69.5
  TOP w0.132: v1(78.99,29.86) 79.14,29.72 U8.16 ; v1(37.93,34.25) 37.93,34.25 37.93,48.17 35.44,50.66 J3.85
  ART03 w0.152: v1(78.99,29.86) 78.49,29.36 77.22,29.36 76.91,29.67 76.91,30.43 75.97,31.37 72.49,31.37 72.27,31.59 72.27,32 72.11,32.16 70.69,32.16 70.54,32 70.54,31.7 70.39,31.55 69.95,31.55 69.8,31.7 69.8,32.03 69.65,32.18 69.34,32.18 69.19,32.03 69.19,31.72 69.04,31.57 68.63,31.57 67.49,32.72 67.03,32.72 65.56,34.19 60.27,34.19 59.88,33.79 38.39,33.79 v1(37.93,34.25)
ETH1_TXD3_M0: length 68.6
  TOP w0.132: v1(40.12,34.25) 40.12,49.6 36.94,52.77 J3.91 ; v1(77.39,29.86) 77.88,30.35 79.12,30.35 79.35,30.12 U8.15
  ART03 w0.152: v1(40.12,34.25) 40.17,34.3 59.67,34.3 60.07,34.7 66.29,34.7 68.3,32.69 72.61,32.69 72.78,32.51 72.78,32.03 72.94,31.88 73.24,31.88 73.39,32.03 73.39,32.61 73.55,32.77 73.83,32.77 74,32.59 74,32.03 74.16,31.88 74.46,31.88 74.61,32.03 74.61,32.36 74.77,32.51 75.74,32.51 76.43,31.83 77.09,31.83 77.39,31.52 v1(77.39,29.86)
FAN_CTRL: length 170.7
  TOP w0.107: v1(33.09,17.01) 33.17,16.93 33.17,13.24 33.93,12.47 33.93,9.75 31.7,7.52 25.61,7.52 25.4,7.3 25.4,2.16 25.78,1.78 95.25,1.78 96.39,2.92 96.39,6.48 101.65,11.73 101.65,14.07 102.82,15.24 104.51,15.24 R13.1 ; v1(36.62,58.25) 35.45,58.25 34.81,58.89 26.46,58.89 26.19,59.16 26.19,59.64 25.69,60.14 J3.46
  BOTTOM w0.107: v1(33.09,17.01) 31.85,18.25 31.85,19.18 32.5,19.82 32.5,27.62 33.6,28.73 33.6,36.58 34.32,37.29 34.32,49.28 35.18,50.14 35.18,53.77 36.22,54.81 36.22,57.84 v1(36.62,58.25)
FUSB302_INT: length 59.7
  TOP w0.107: J3.232 74.19,67.54 72.77,68.96 72.77,74.14 v1(71.98,74.93)
  BOTTOM w0.107: v1(71.98,74.93) 72.16,75.11 72.16,82.91 71.75,83.31 58.7,83.31 58.17,83.85 55.22,83.85 54.25,82.88 54.25,80.31 52.58,78.64 52.58,74.96 54.13,73.41 54.13,69.47 53.49,68.83 50.62,68.83 50.27,69.19 R109.2 50.34,69.85 U11.5
HDMI_5V: length 10.3
  TOP w0.635: J33.18 98.15,71.47 98.15,69.29 97.64,68.78 95.91,68.78 94.65,67.52 90.98,67.52
HDMI_TX_CEC_M0: length 240.5
  TOP w0.107: v1(40.62,58.25) 42.71,58.25 43.44,57.52 J3.117
  ART03 w0.107: v1(107.91,8.13) 107.29,8.75 107.29,20.72 105.87,22.15 105.87,35.86 109.93,39.93 110.69,39.93 112.34,41.58 112.34,45.39 112.01,45.72 112.01,46.96 v1(111.5,47.48)
  BOTTOM w0.107: R152.1 79.17,64.91 79.17,66.6 78.49,67.28 76.28,67.28 71.73,62.74 71.73,57 74.3,54.43 74.3,50.77 77.57,47.5 95.1,47.5 95.61,48.01 96.62,48.01 97.13,47.5 102.03,47.5 103.66,49.12 109.86,49.12 v1(111.5,47.48) ; v1(40.62,58.25) 40.62,58 39.24,56.62 39.24,36.3 38.34,35.39 38.34,32.95 37.74,32.36 37.74,31.32 38.44,30.62 38.44,27.85 37.39,26.8 37.39,23.77 40.52,20.65 40.52,9.88 42.29,8.1 42.29,5.14 44.96,2.46 65.07,2.46 67.83,5.22 105.85,5.22 107.91,7.28 v1(107.91,8.13)
HDMI_TX_CEC_PORT: length 21.2
  TOP w0.107: v1(85.06,69.09) 85.61,69.64 D43.2 86.41,70.68 86.63,70.89 90.98,70.89 94.63,74.53 J33.13
  BOTTOM w0.107: v1(85.06,69.09) 84.61,68.63 83.46,68.63 82.18,67.35 Q10.3
HDMI_TX_D0N: length 50.6
  TOP w0.107: J3.248 78.19,62.71 arc(78.18,62.65) 78.14,62.6 78.13,62.58 arc(78.1,62.53) 78.08,62.47 78.08,62.32 arc(78.05,62.13) 77.94,61.98 77.79,61.82 arc(77.72,61.72) 77.69,61.59 v1(77.69,61.44)
  BOTTOM w0.107: v1(77.69,61.44) 77.67,61.44 arc(77.53,61.5) 77.48,61.64 77.48,61.7 arc(77.44,61.86) 77.35,61.99 arc(77.2,62.1) 77.01,62.13 76.36,62.13 75.67,61.44 arc(75.55,61.27) 75.51,61.06 75.51,60.36 arc(75.61,59.84) 75.9,59.41 76.32,58.99 arc(77.01,58.53) 77.83,58.36 92.61,58.36 arc(93,58.53) 93.16,58.92 93.16,59.85 arc(93.43,60.12) 93.7,59.85 93.7,58.92 arc(93.86,58.53) 94.25,58.36 97.03,58.36 arc(97.42,58.53) 97.58,58.92 97.58,59.7 arc(97.85,59.96) 98.11,59.7 98.11,58.95 arc(98.67,58.39) 99.22,58.95 99.22,59.88 arc(99.48,60.14) 99.75,59.88 99.75,58.92 arc(99.91,58.53) 100.3,58.36 100.46,58.36 arc(100.94,58.56) 101.14,59.04 101.14,59.6 arc(101.22,59.79) 101.41,59.86 arc(101.6,59.78) 101.67,59.6 101.67,58.92 arc(101.83,58.53) 102.22,58.36 102.35,58.36 arc(102.81,58.56) 103.01,59.02 103.01,59.5 arc(102.89,60.09) 102.55,60.59 102.53,60.61 arc(102.03,60.95) 101.43,61.07 100.51,61.07 arc(100.44,61.1) 100.41,61.17 100.41,61.26 arc(100.44,61.41) 100.53,61.54 C221.1
HDMI_TX_D0N_PORT: length 18.4
  BOTTOM w0.107: J33.9 97.32,77.09 arc(97.24,77.29) 97.04,77.37 96.82,77.37 96.73,77.28 arc(96.68,77.19) 96.66,77.1 96.66,70.57 arc(96.69,70.5) 96.77,70.46 arc(96.84,70.43) 96.88,70.36 96.88,70.15 arc(96.84,70.07) 96.77,70.04 arc(96.69,70.01) 96.66,69.93 96.66,69.85 arc(96.69,69.7) 96.77,69.57 98.18,68.16 arc(98.61,67.87) 99.11,67.77 99.78,67.77 arc(100.22,67.59) 100.41,67.14 100.41,66.76 arc(100.44,66.59) 100.54,66.44 D50.2 100.69,65.9 arc(100.72,65.73) 100.82,65.58 R233.1 100.68,65.15 arc(100.48,64.85) 100.41,64.5 100.41,63.92 arc(100.48,63.57) 100.68,63.27 C221.2
HDMI_TX_D0P: length 50.7
  TOP w0.107: v1(77.69,60.63) 77.69,60.73 arc(77.68,60.81) 77.63,60.87 77.43,61.08 arc(77.31,61.26) 77.27,61.47 77.27,61.49 arc(77.31,61.7) 77.43,61.89 77.71,62.16 arc(77.77,62.26) 77.8,62.39 77.8,62.47 arc(77.79,62.53) 77.75,62.58 77.74,62.6 arc(77.7,62.65) 77.69,62.71 J3.246
  BOTTOM w0.107: v1(77.69,60.63) 77.69,60.73 arc(77.68,60.81) 77.63,60.87 77.34,61.17 arc(77.23,61.33) 77.19,61.52 77.19,61.7 arc(77.18,61.75) 77.15,61.79 arc(77.09,61.83) 77.01,61.85 76.48,61.85 75.87,61.24 arc(75.81,61.16) 75.79,61.06 75.79,60.36 arc(75.87,59.95) 76.11,59.61 76.52,59.19 arc(77.12,58.79) 77.83,58.65 92.61,58.65 arc(92.8,58.73) 92.88,58.92 92.88,59.85 arc(93.43,60.4) 93.98,59.85 93.98,58.92 arc(94.06,58.73) 94.25,58.65 97.03,58.65 arc(97.22,58.73) 97.3,58.92 97.3,59.7 arc(97.85,60.25) 98.4,59.7 98.4,58.95 arc(98.67,58.68) 98.93,58.95 98.93,59.88 arc(99.48,60.43) 100.04,59.88 100.04,58.92 arc(100.11,58.73) 100.3,58.65 100.46,58.65 arc(100.74,58.76) 100.85,59.04 100.85,59.6 arc(101.02,59.99) 101.42,60.15 arc(101.8,59.98) 101.96,59.6 101.96,58.92 arc(102.03,58.73) 102.22,58.65 102.35,58.65 arc(102.61,58.76) 102.72,59.02 102.72,59.5 arc(102.62,59.98) 102.35,60.39 102.33,60.41 arc(101.92,60.69) 101.43,60.78 100.51,60.78 arc(100.24,60.9) 100.12,61.17 100.12,61.21 arc(100.08,61.41) 99.97,61.59 C220.1
HDMI_TX_D0P_PORT: length 18.4
  BOTTOM w0.107: J33.7 97.06,77.74 arc(96.96,77.68) 96.85,77.65 96.71,77.65 96.53,77.48 arc(96.41,77.3) 96.37,77.1 96.37,69.85 arc(96.42,69.59) 96.57,69.37 97.98,67.95 arc(98.5,67.61) 99.11,67.49 99.78,67.49 arc(100.02,67.39) 100.12,67.14 100.12,66.76 arc(100.09,66.59) 99.99,66.44 D49.2 99.84,65.9 arc(99.81,65.73) 99.71,65.58 R234.1 99.85,65.15 arc(100.06,64.85) 100.13,64.49 100.13,63.93 arc(100.06,63.57) 99.85,63.27 C220.2
HDMI_TX_D1N: length 50.9
  TOP w0.107: v1(77.69,65.15) 77.69,65.18 arc(77.62,65.35) 77.44,65.43 77.3,65.43 arc(77.15,65.36) 77.08,65.21 77.08,65.1 arc(77.09,65.06) 77.11,65.02 77.14,65 arc(77.18,64.94) 77.19,64.87 J3.244
  BOTTOM w0.107: v1(77.69,65.15) 77.61,65.07 arc(77.56,65) 77.55,64.92 77.55,64.79 arc(77.4,64.43) 77.05,64.29 76.19,64.29 arc(75.54,64.16) 74.99,63.79 73.87,62.67 arc(73.58,62.24) 73.48,61.72 73.48,59.36 arc(73.57,58.87) 73.85,58.46 75.6,56.71 arc(76.02,56.43) 76.51,56.33 104.21,56.33 arc(104.91,56.47) 105.51,56.87 107.53,58.89 arc(107.69,59.12) 107.74,59.41 107.74,60.47 arc(107.71,60.55) 107.62,60.59 arc(107.53,60.63) 107.49,60.72 107.49,60.89 arc(107.53,60.98) 107.62,61.02 arc(107.71,61.05) 107.74,61.14 107.74,61.24 arc(107.7,61.43) 107.6,61.59 107.2,61.98 C219.1
HDMI_TX_D1N_PORT: length 23.4
  BOTTOM w0.107: J33.6 98.32,78.67 arc(98.42,78.92) 98.67,79.02 99.13,79.02 arc(99.28,78.99) 99.41,78.9 99.46,78.85 arc(99.5,78.76) 99.46,78.67 arc(99.42,78.58) 99.46,78.49 99.58,78.37 arc(99.67,78.33) 99.76,78.37 arc(99.85,78.41) 99.94,78.37 100.06,78.25 arc(100.1,78.16) 100.06,78.07 arc(100.02,77.98) 100.06,77.89 100.18,77.77 arc(100.27,77.73) 100.36,77.77 arc(100.45,77.81) 100.54,77.77 100.67,77.65 arc(100.7,77.56) 100.67,77.47 arc(100.63,77.38) 100.67,77.29 100.79,77.16 arc(100.88,77.13) 100.97,77.16 arc(101.06,77.2) 101.15,77.16 101.27,77.04 arc(101.31,76.95) 101.27,76.86 arc(101.23,76.77) 101.27,76.68 101.39,76.56 arc(101.48,76.52) 101.57,76.56 arc(101.66,76.6) 101.75,76.56 102.58,75.73 arc(102.8,75.41) 102.87,75.04 102.87,74.69 arc(103.08,73.65) 103.67,72.76 106.17,70.26 arc(106.21,70.17) 106.17,70.08 arc(106.13,69.99) 106.17,69.9 106.29,69.78 arc(106.38,69.74) 106.47,69.78 106.47,69.78 arc(106.56,69.82) 106.65,69.78 106.77,69.66 arc(106.81,69.57) 106.77,69.48 arc(106.74,69.39) 106.77,69.3 106.9,69.18 arc(106.99,69.14) 107.08,69.18 arc(107.17,69.21) 107.26,69.18 107.61,68.82 arc(107.71,68.67) 107.74,68.5 107.74,68.4 arc(107.71,68.32) 107.63,68.28 arc(107.55,68.25) 107.52,68.17 107.52,67.97 arc(107.55,67.89) 107.63,67.86 arc(107.71,67.82) 107.74,67.74 107.74,67.54 arc(107.71,67.46) 107.63,67.43 arc(107.55,67.4) 107.52,67.32 107.52,67.12 arc(107.55,67.04) 107.63,67 arc(107.71,66.97) 107.74,66.89 107.74,66.76 arc(107.71,66.59) 107.61,66.44 D56.2 107.46,65.9 arc(107.43,65.73) 107.33,65.58 R231.1 107.47,65.15 arc(107.67,64.85) 107.74,64.5 107.74,63.92 arc(107.67,63.57) 107.47,63.27 C219.2
HDMI_TX_D1P: length 52.8
  TOP w0.107: v1(77.69,65.96) 77.69,65.96 arc(77.62,65.78) 77.44,65.71 77.3,65.71 arc(76.94,65.56) 76.8,65.21 76.8,65.1 arc(76.79,65.06) 76.77,65.02 76.74,65 arc(76.7,64.94) 76.69,64.87 J3.242
  BOTTOM w0.107: v1(77.69,65.96) 77.47,65.74 arc(77.32,65.51) 77.26,65.24 77.26,64.79 arc(77.2,64.63) 77.05,64.57 76.19,64.57 arc(75.43,64.42) 74.79,63.99 73.67,62.87 arc(73.32,62.35) 73.19,61.72 73.19,59.36 arc(73.31,58.76) 73.65,58.25 75.4,56.51 arc(75.91,56.17) 76.51,56.05 104.21,56.05 arc(105.02,56.21) 105.72,56.67 107.73,58.68 arc(107.95,59.02) 108.03,59.41 108.03,61.21 arc(108.07,61.41) 108.18,61.58 C218.1
HDMI_TX_D1P_PORT: length 21.5
  BOTTOM w0.107: J33.4 98.6,79.45 arc(98.77,79.34) 98.97,79.3 99.13,79.3 arc(99.39,79.25) 99.61,79.1 102.78,75.93 arc(103.06,75.52) 103.15,75.04 103.15,74.69 arc(103.34,73.76) 103.87,72.96 106.37,70.46 arc(106.37,70.46) 106.37,70.46 107.81,69.02 arc(107.97,68.78) 108.03,68.5 108.03,66.72 arc(108.06,66.59) 108.13,66.47 D55.2 108.31,65.9 arc(108.34,65.73) 108.44,65.58 R232.1 108.3,65.15 arc(108.1,64.85) 108.03,64.49 108.03,63.93 arc(108.1,63.57) 108.3,63.27 C218.2
HDMI_TX_D2N: length 34
  TOP w0.107: v1(76.69,61.44) 76.47,61.22 arc(76.42,61.19) 76.37,61.18 76.34,61.18 arc(76.29,61.19) 76.25,61.22 76.17,61.29 arc(76.1,61.4) 76.07,61.53 76.07,62.46 arc(76.09,62.52) 76.12,62.58 76.14,62.59 arc(76.18,62.65) 76.19,62.72 J3.240
  BOTTOM w0.107: v1(76.69,61.44) 76.69,61.35 76.46,61.12 arc(76.33,60.93) 76.28,60.7 76.28,60.37 arc(76.32,60.16) 76.44,59.98 76.79,59.64 arc(77.32,59.28) 77.96,59.15 83.44,59.15 arc(83.79,59.3) 83.94,59.65 arc(84.2,59.91) 84.47,59.65 84.47,59.53 arc(84.58,59.26) 84.85,59.15 85.08,59.15 arc(85.43,59.3) 85.57,59.65 arc(85.84,59.91) 86.11,59.65 86.11,59.53 arc(86.22,59.26) 86.49,59.15 86.71,59.15 arc(87.06,59.3) 87.21,59.65 arc(87.48,59.91) 87.74,59.65 87.74,59.53 arc(87.85,59.26) 88.12,59.15 88.35,59.15 arc(88.7,59.3) 88.85,59.65 arc(89.11,59.91) 89.38,59.65 89.38,59.53 arc(89.49,59.26) 89.76,59.15 89.99,59.15 arc(90.34,59.3) 90.48,59.65 arc(90.75,59.91) 91.01,59.65 91.01,59.53 arc(91.13,59.26) 91.4,59.15 91.58,59.15 arc(91.97,59.31) 92.13,59.69 92.13,60.63 arc(92.18,60.77) 92.32,60.83 92.44,60.83 arc(92.76,60.89) 93.02,61.07 93.11,61.15 arc(93.28,61.27) 93.49,61.31 96.07,61.31 arc(96.12,61.3) 96.16,61.28 96.36,61.07 arc(96.68,60.86) 97.06,60.78 97.24,60.78 arc(97.47,60.83) 97.67,60.96 97.87,61.16 97.87,61.31 arc(97.89,61.42) 97.96,61.52 C217.1
HDMI_TX_D2N_PORT: length 35.3
  BOTTOM w0.107: J33.3 97.15,80.48 arc(96.97,80.6) 96.77,80.64 96.5,80.64 arc(96.27,80.59) 96.08,80.47 96.06,80.45 arc(95.93,80.25) 95.89,80.03 95.89,77.81 arc(95.72,77.42) 95.33,77.26 93.62,77.26 arc(93.35,76.99) 93.62,76.72 95.23,76.72 arc(95.69,76.53) 95.89,76.07 95.89,75.94 arc(95.72,75.55) 95.33,75.39 93.06,75.39 arc(92.79,75.12) 93.06,74.85 95.26,74.85 arc(95.81,74.3) 95.26,73.75 93.06,73.75 arc(92.79,73.48) 93.06,73.22 95.17,73.22 arc(95.68,73.01) 95.89,72.5 95.89,69.59 arc(95.96,69.22) 96.17,68.9 97.65,67.42 arc(97.81,67.18) 97.87,66.9 97.87,66.76 arc(97.9,66.59) 98,66.44 D54.2 98.15,65.9 arc(98.18,65.73) 98.28,65.58 R229.1 98.14,65.15 arc(97.94,64.85) 97.87,64.5 97.87,63.92 arc(97.94,63.57) 98.14,63.27 C217.2
HDMI_TX_D2P: length 33.2
  TOP w0.107: J3.238 75.69,62.7 arc(75.7,62.65) 75.73,62.61 75.75,62.59 arc(75.78,62.54) 75.79,62.49 75.79,61.53 arc(75.84,61.29) 75.97,61.09 76.04,61.02 arc(76.18,60.93) 76.34,60.89 76.36,60.89 arc(76.42,60.88) 76.48,60.84 v1(76.69,60.63)
  BOTTOM w0.107: v1(76.69,60.63) 76.62,60.56 arc(76.58,60.5) 76.57,60.43 76.57,60.37 arc(76.59,60.27) 76.65,60.18 76.99,59.84 arc(77.43,59.54) 77.96,59.44 83.44,59.44 arc(83.59,59.5) 83.65,59.65 arc(84.2,60.2) 84.75,59.65 84.75,59.53 arc(84.78,59.46) 84.85,59.44 85.08,59.44 arc(85.23,59.5) 85.29,59.65 arc(85.84,60.2) 86.39,59.65 86.39,59.53 arc(86.42,59.46) 86.49,59.44 86.71,59.44 arc(86.86,59.5) 86.92,59.65 arc(87.48,60.2) 88.03,59.65 88.03,59.53 arc(88.06,59.46) 88.12,59.44 88.35,59.44 arc(88.5,59.5) 88.56,59.65 arc(89.11,60.2) 89.66,59.65 89.66,59.53 arc(89.69,59.46) 89.76,59.44 89.99,59.44 arc(90.13,59.5) 90.2,59.65 arc(90.75,60.2) 91.3,59.65 91.3,59.53 arc(91.33,59.46) 91.4,59.44 91.58,59.44 arc(91.77,59.51) 91.84,59.69 91.84,60.63 arc(91.98,60.97) 92.32,61.11 92.44,61.11 arc(92.65,61.15) 92.82,61.27 92.9,61.35 arc(93.17,61.53) 93.49,61.59 94.5,61.59 arc(94.58,61.63) 94.61,61.71 arc(94.65,61.79) 94.73,61.82 94.92,61.82 arc(95.01,61.79) 95.04,61.71 arc(95.07,61.63) 95.15,61.59 95.35,61.59 arc(95.43,61.63) 95.47,61.71 arc(95.5,61.79) 95.58,61.82 95.78,61.82 arc(95.86,61.79) 95.89,61.71 arc(95.93,61.63) 96.01,61.59 96.07,61.59 arc(96.23,61.56) 96.36,61.48 96.56,61.27 arc(96.79,61.12) 97.06,61.07 97.24,61.07 arc(97.36,61.09) 97.47,61.16 97.59,61.28 97.59,61.36 arc(97.58,61.42) 97.54,61.47 C216.1
HDMI_TX_D2P_PORT: length 36.1
  BOTTOM w0.107: C216.2 97.31,63.27 arc(97.52,63.57) 97.59,63.93 97.59,64.49 arc(97.52,64.85) 97.31,65.15 R230.1 97.17,65.58 arc(97.27,65.73) 97.3,65.9 D53.2 97.45,66.44 arc(97.55,66.59) 97.58,66.76 97.58,66.9 arc(97.55,67.07) 97.45,67.22 95.97,68.7 arc(95.7,69.11) 95.6,69.59 95.6,72.5 arc(95.47,72.81) 95.17,72.93 93.06,72.93 arc(92.51,73.48) 93.06,74.04 95.26,74.04 arc(95.52,74.3) 95.26,74.57 93.06,74.57 arc(92.51,75.12) 93.06,75.67 95.33,75.67 arc(95.52,75.75) 95.6,75.94 95.6,76.07 arc(95.49,76.33) 95.23,76.44 93.62,76.44 arc(93.07,76.99) 93.62,77.54 95.33,77.54 arc(95.52,77.62) 95.6,77.81 95.6,80.03 arc(95.67,80.36) 95.86,80.65 95.88,80.67 arc(96.16,80.86) 96.5,80.92 97,80.92 arc(97.23,81.02) 97.32,81.24 J33.1
HDMI_TX_D3N: length 50.3
  TOP w0.107: J3.254 79.69,62.73 arc(79.68,62.65) 79.63,62.59 79.62,62.57 arc(79.57,62.51) 79.56,62.43 79.56,61.66 arc(79.57,61.58) 79.62,61.51 v1(79.69,61.44)
  BOTTOM w0.107: v1(79.69,61.44) 79.69,61.44 arc(79.77,61.47) 79.8,61.55 79.8,61.56 arc(79.79,61.62) 79.75,61.68 78.32,63.11 arc(78.01,63.32) 77.63,63.39 75.94,63.39 arc(75.75,63.36) 75.59,63.25 74.39,62.05 arc(74.29,61.89) 74.25,61.7 74.25,59.72 arc(74.35,59.21) 74.64,58.79 75.8,57.62 arc(76.37,57.24) 77.05,57.1 104.03,57.1 arc(104.47,57.19) 104.84,57.44 104.88,57.48 arc(105.12,57.84) 105.2,58.25 105.2,58.56 arc(105.36,58.95) 105.75,59.11 105.94,59.11 arc(106.12,59.18) 106.19,59.36 106.19,59.38 arc(106.11,59.56) 105.93,59.64 105.75,59.64 arc(105.36,59.8) 105.2,60.19 105.2,60.5 arc(105.16,60.59) 105.06,60.63 arc(104.97,60.67) 104.93,60.77 104.93,60.92 arc(104.97,61.02) 105.06,61.06 arc(105.16,61.1) 105.2,61.2 105.2,61.72 arc(105.12,61.91) 104.94,61.98 C223.1
HDMI_TX_D3N_PORT: length 21.6
  BOTTOM w0.107: J33.12 98.32,75.38 arc(98.37,75.5) 98.49,75.55 98.99,75.55 arc(99.07,75.52) 99.11,75.43 arc(99.14,75.35) 99.23,75.31 99.42,75.31 arc(99.5,75.35) 99.54,75.43 arc(99.57,75.52) 99.66,75.55 99.84,75.55 arc(99.93,75.52) 99.96,75.43 arc(100,75.35) 100.08,75.31 100.27,75.31 arc(100.35,75.35) 100.39,75.43 arc(100.42,75.52) 100.51,75.55 100.7,75.55 arc(100.78,75.52) 100.82,75.43 arc(100.85,75.35) 100.94,75.31 101.12,75.31 arc(101.21,75.35) 101.24,75.43 arc(101.28,75.52) 101.36,75.55 101.55,75.55 arc(101.66,75.53) 101.76,75.46 101.89,75.33 arc(102.04,75.1) 102.1,74.83 102.1,73.22 arc(102.15,72.94) 102.32,72.69 102.63,72.38 arc(102.67,72.27) 102.63,72.15 arc(102.58,72.04) 102.63,71.92 102.7,71.85 arc(102.81,71.8) 102.93,71.85 arc(103.04,71.9) 103.16,71.85 103.32,71.69 arc(103.37,71.58) 103.32,71.48 arc(103.28,71.38) 103.32,71.28 103.42,71.18 arc(103.52,71.14) 103.63,71.18 arc(103.73,71.22) 103.83,71.18 103.93,71.08 arc(103.97,70.98) 103.93,70.88 arc(103.89,70.77) 103.93,70.67 104.02,70.57 arc(104.13,70.53) 104.23,70.57 arc(104.33,70.62) 104.44,70.57 104.53,70.48 arc(104.57,70.38) 104.53,70.27 arc(104.49,70.17) 104.53,70.07 104.63,69.97 arc(104.73,69.93) 104.83,69.97 arc(104.94,70.01) 105.04,69.97 105.08,69.93 arc(105.17,69.79) 105.2,69.63 105.2,69.29 arc(105.16,69.19) 105.07,69.15 arc(104.97,69.11) 104.93,69.01 104.93,68.86 arc(104.97,68.76) 105.07,68.72 arc(105.16,68.68) 105.2,68.58 105.2,68.43 arc(105.16,68.34) 105.07,68.3 arc(104.97,68.25) 104.93,68.16 104.93,68.01 arc(104.97,67.91) 105.07,67.87 arc(105.16,67.83) 105.2,67.73 105.2,67.5 arc(105.17,67.41) 105.08,67.37 arc(104.99,67.33) 104.95,67.25 104.95,67.07 arc(104.99,66.98) 105.08,66.94 arc(105.17,66.91) 105.2,66.82 105.2,66.75 arc(105.17,66.59) 105.08,66.45 D52.2 104.92,65.9 arc(104.89,65.73) 104.79,65.58 R227.1 104.93,65.15 arc(105.14,64.85) 105.21,64.49 105.21,63.3 arc(105.11,63.08) 104.89,62.98 C223.2
HDMI_TX_D3P: length 53.4
  TOP w0.107: J3.252 79.19,62.69 arc(79.2,62.65) 79.22,62.61 79.24,62.6 arc(79.26,62.56) 79.27,62.52 79.27,61.48 arc(79.31,61.28) 79.42,61.11 79.62,60.92 arc(79.67,60.84) 79.69,60.75 v1(79.69,60.63)
  BOTTOM w0.107: C222.1 105.76,61.7 arc(105.56,61.4) 105.49,61.04 105.49,60.19 arc(105.56,60.01) 105.75,59.93 105.93,59.93 arc(106.32,59.77) 106.48,59.38 106.48,59.36 arc(106.32,58.98) 105.94,58.82 105.75,58.82 arc(105.56,58.75) 105.49,58.56 105.49,58.25 arc(105.38,57.73) 105.08,57.28 105.04,57.24 arc(104.58,56.93) 104.03,56.82 77.05,56.82 arc(76.26,56.98) 75.6,57.42 74.44,58.58 arc(74.09,59.11) 73.96,59.72 73.96,61.7 arc(74.02,62) 74.19,62.25 75.39,63.45 arc(75.64,63.62) 75.94,63.68 77.63,63.68 arc(78.12,63.58) 78.52,63.31 80.02,61.82 arc(80.15,61.5) 80.02,61.19 79.76,60.94 arc(79.71,60.85) 79.69,60.76 v1(79.69,60.63)
